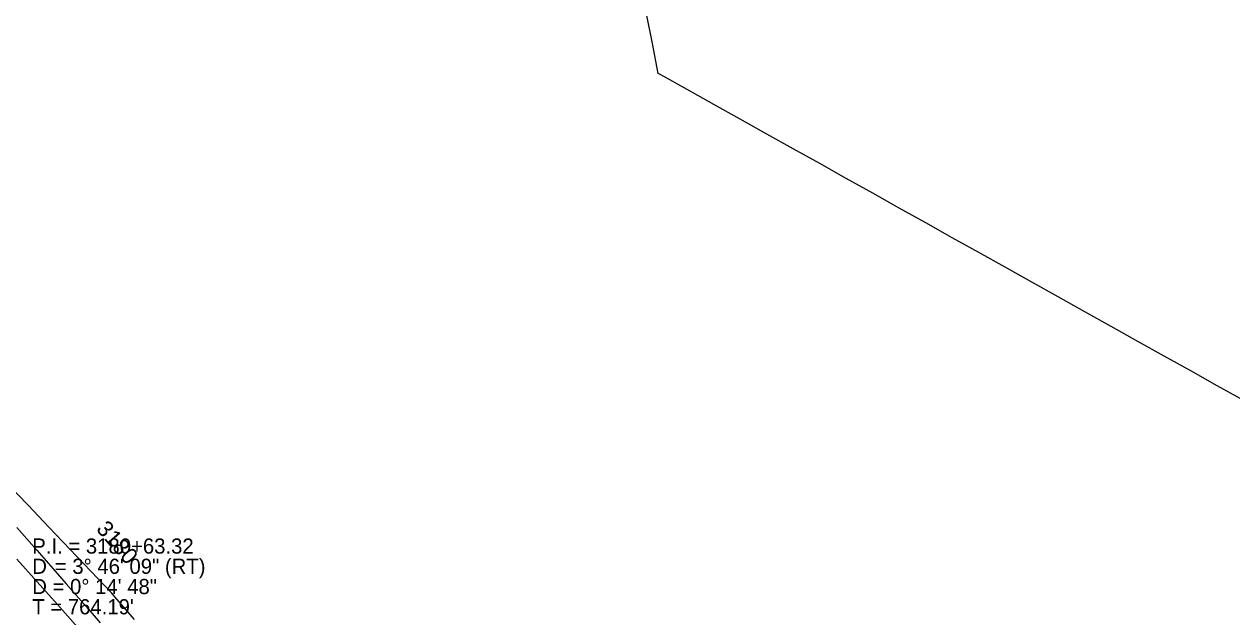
# Model space of a CAD drawing. Extents: x 2132221 to 2141942, y 535736 to 547298.
# Drawn here: x 2136476 to 2137073, y 542712 to 543005 of the extents above; entities that cross this region are included whole.
import ezdxf

# ---------------------------------------------------------------- set-up
doc = ezdxf.new("R2010")
doc.units = 0
for name, color, linetype in [('RD_EX_Misc', 7, 'Continuous'), ('RD_EX_Road', 7, 'Continuous'), ('RD_EX_VEG', 7, 'Continuous'), ('RD_HC_Cl', 7, 'Continuous'), ('RD_HC_Data', 7, 'Continuous'), ('RD_HC_TX_Sta50', 7, 'Continuous'), ('TOPO_E_TLIML-Line', 7, 'Continuous')]:
    doc.layers.add(name, color=color, linetype=linetype)

msp = doc.modelspace()

# ---------------------------------------------------------------- linework, layer by layer
at = {"layer": 'RD_EX_Misc'}
msp.add_lwpolyline([(2136472.45, 542740.3), (2136482.43, 542729.11), (2136492.42, 542717.91), (2136502.4, 542706.72)], dxfattribs=at)
at = {"layer": 'RD_EX_Road'}
msp.add_lwpolyline([(2136472.42, 542756), (2136482.26, 542744.68), (2136486.81, 542739.44), (2136496.68, 542728.14), (2136506.56, 542716.85), (2136513.52, 542708.88)], dxfattribs=at)
at = {"layer": 'RD_EX_VEG'}
msp.add_lwpolyline([(2136530.56, 542710.37), (2136520.75, 542721.72), (2136519.29, 542723.42), (2136508.95, 542734.28), (2136498.6, 542745.15), (2136488.26, 542756.01), (2136477.92, 542766.88), (2136467.58, 542777.74)], dxfattribs=at)
at = {"layer": 'RD_HC_Cl'}
msp.add_arc((2118950.8, 527389.88), 23225.51, 39.112741, 42.881786, dxfattribs=at)
at = {"layer": 'TOPO_E_TLIML-Line'}
msp.add_lwpolyline([(2137078.55, 542818.65), (2137065.46, 542825.97), (2137052.36, 542833.29), (2137039.27, 542840.61), (2137026.18, 542847.93), (2137013.08, 542855.25), (2136999.99, 542862.56), (2136986.9, 542869.88), (2136973.8, 542877.2), (2136960.71, 542884.52), (2136947.62, 542891.84), (2136934.52, 542899.16), (2136921.43, 542906.48), (2136908.34, 542913.79), (2136895.24, 542921.11), (2136882.15, 542928.43), (2136869.06, 542935.75), (2136855.96, 542943.07), (2136842.87, 542950.39), (2136829.78, 542957.71), (2136816.68, 542965.03), (2136803.59, 542972.34), (2136790.5, 542979.66), (2136789.2, 542980.39), (2136786.36, 542995.11), (2136783.51, 543009.84)], dxfattribs=at)

# ---------------------------------------------------------------- texts
at = {"layer": 'RD_HC_Data'}
for s, p in [('P.I. = 3180+63.32', (2136480, 542743)), ('D', (2136480, 542733)), ('    = 3%%d 46\' 09" (RT)', (2136480, 542733)), ('D = 0%%d 14\' 48"', (2136480, 542723)), ("T = 764.19'", (2136480, 542713))]:
    msp.add_text(s, height=7.5, dxfattribs=at).set_placement(p)
at = {"layer": 'RD_HC_TX_Sta50'}
msp.add_text('3180', height=8, rotation=311.1528, dxfattribs=at).set_placement((2136511.21, 542754.92))

doc.saveas('drawing.dxf')
